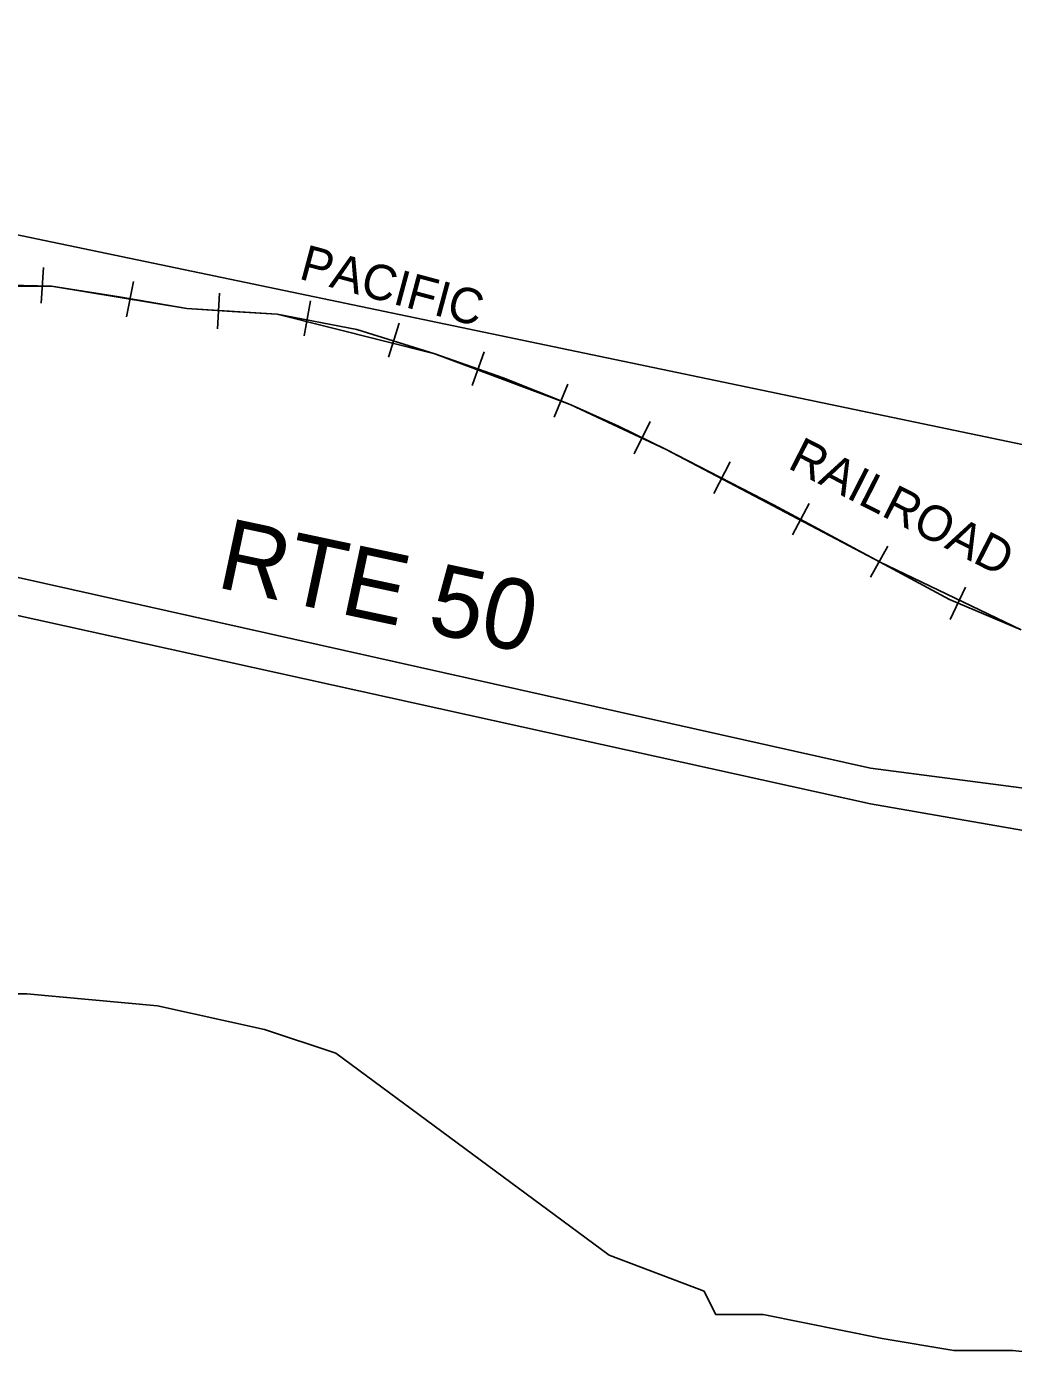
# Model space of a CAD drawing. Extents: x 5.01 to 9.58, y 0.27 to 3.39.
# Drawn here: x 8.0366 to 8.3602, y 2.5344 to 2.9725 of the extents above; entities that cross this region are included whole.
import ezdxf

# ---------------------------------------------------------------- set-up
doc = ezdxf.new("R2010")
doc.units = 0
doc.layers.add('MO_001_NOSHOW', color=7, linetype='Continuous')
doc.layers.add('MO_001_VIEW_PV', color=7, linetype='Continuous')

msp = doc.modelspace()

# ---------------------------------------------------------------- linework, layer by layer
at = {"layer": 'MO_001_NOSHOW'}
for points in [[(7.7064, 2.97253), (8.91442, 2.72047)], [(8.36283, 2.77467), (8.31661, 2.79686), (8.24634, 2.83384), (8.2149, 2.84863), (8.17052, 2.86527), (8.11875, 2.87822), (8.08916, 2.88007), (8.04479, 2.88746), (8.00781, 2.88746)]]:
    msp.add_lwpolyline(points, dxfattribs=at)
at = {"layer": 'MO_001_VIEW_PV'}
for p, q in [((8.0414, 2.88183), (8.04212, 2.89357)), ((8.06936, 2.87734), (8.07168, 2.88894)), ((8.09922, 2.87343), (8.09981, 2.88517)), ((8.12763, 2.87111), (8.12967, 2.88256)), ((8.15532, 2.86415), (8.15879, 2.87531)), ((8.18271, 2.85487), (8.18663, 2.86589)), ((8.20967, 2.84444), (8.21416, 2.85531)), ((8.23591, 2.83241), (8.24113, 2.84299)), ((8.26199, 2.81937), (8.26735, 2.82981)), ((8.2878, 2.80588), (8.2933, 2.81617)), ((8.31345, 2.79197), (8.31909, 2.80212)), ((8.33954, 2.77806), (8.34461, 2.78863)), ((8.03662, 2.65529), (8.00154, 2.65529)), ((8.07951, 2.65138), (8.03662, 2.65529)), ((8.27823, 2.55007), (8.26272, 2.55007)), ((8.31722, 2.54224), (8.27823, 2.55007)), ((8.3407, 2.53833), (8.31722, 2.54224)), ((8.36012, 2.53833), (8.3407, 2.53833)), ((8.3952, 2.53442), (8.36012, 2.53833))]:
    msp.add_line(p, q, dxfattribs=at)
for points in [[(8.36283, 2.77467), (8.33928, 2.78468), (8.31661, 2.79686), (8.28163, 2.81574), (8.24634, 2.83384), (8.23071, 2.84146), (8.2149, 2.84863), (8.19292, 2.85738), (8.17052, 2.86527), (8.14491, 2.87325), (8.11875, 2.87822), (8.10397, 2.87911), (8.08916, 2.88007), (8.06695, 2.88388), (8.04479, 2.88746), (8.02635, 2.88789)], [(7.04649, 2.69035), (7.08937, 2.69424), (7.12835, 2.69814), (7.2258, 2.70984), (7.28817, 2.71763), (7.33884, 2.72543), (7.36224, 2.72932), (7.4285, 2.74883), (7.45579, 2.75662), (7.50646, 2.78), (7.61561, 2.83067), (7.65069, 2.84238), (7.70137, 2.85407), (7.79102, 2.84628), (7.86507, 2.83067), (7.93525, 2.81898), (7.96254, 2.81119), (8.01711, 2.79559), (8.31338, 2.72932), (8.40302, 2.71763), (8.41472, 2.71763), (8.43031, 2.71763)], [(7.04649, 2.67866), (7.09327, 2.68255), (7.12835, 2.68645), (7.2531, 2.70205), (7.28817, 2.70593), (7.33884, 2.71374), (7.36613, 2.71763), (7.37782, 2.72153), (7.40511, 2.72932), (7.4168, 2.73322), (7.4324, 2.73712), (7.45969, 2.74491), (7.47917, 2.75662), (7.51036, 2.76831), (7.6234, 2.82288), (7.65069, 2.83067), (7.70137, 2.84238), (7.78713, 2.83457), (7.86507, 2.81898), (7.93525, 2.80729), (7.95864, 2.7995), (8.01321, 2.7839), (8.31338, 2.71763), (8.37113, 2.70759)], [(8.26269, 2.55001), (8.25879, 2.5578), (8.22762, 2.56952), (8.13796, 2.63577), (8.11456, 2.64356), (8.07948, 2.65136)]]:
    msp.add_lwpolyline(points, dxfattribs=at)

# ---------------------------------------------------------------- texts
for s, height, rotation, p in [('PACIFIC', 0.011594, 345, (8.12553, 2.88994)), ('RAILROAD', 0.011594, 333, (8.28585, 2.82794)), ('RTE 50', 0.023189, 348, (8.09833, 2.78875))]:
    msp.add_text(s, height=height, rotation=rotation, dxfattribs=at).set_placement(p)

doc.saveas('drawing.dxf')
